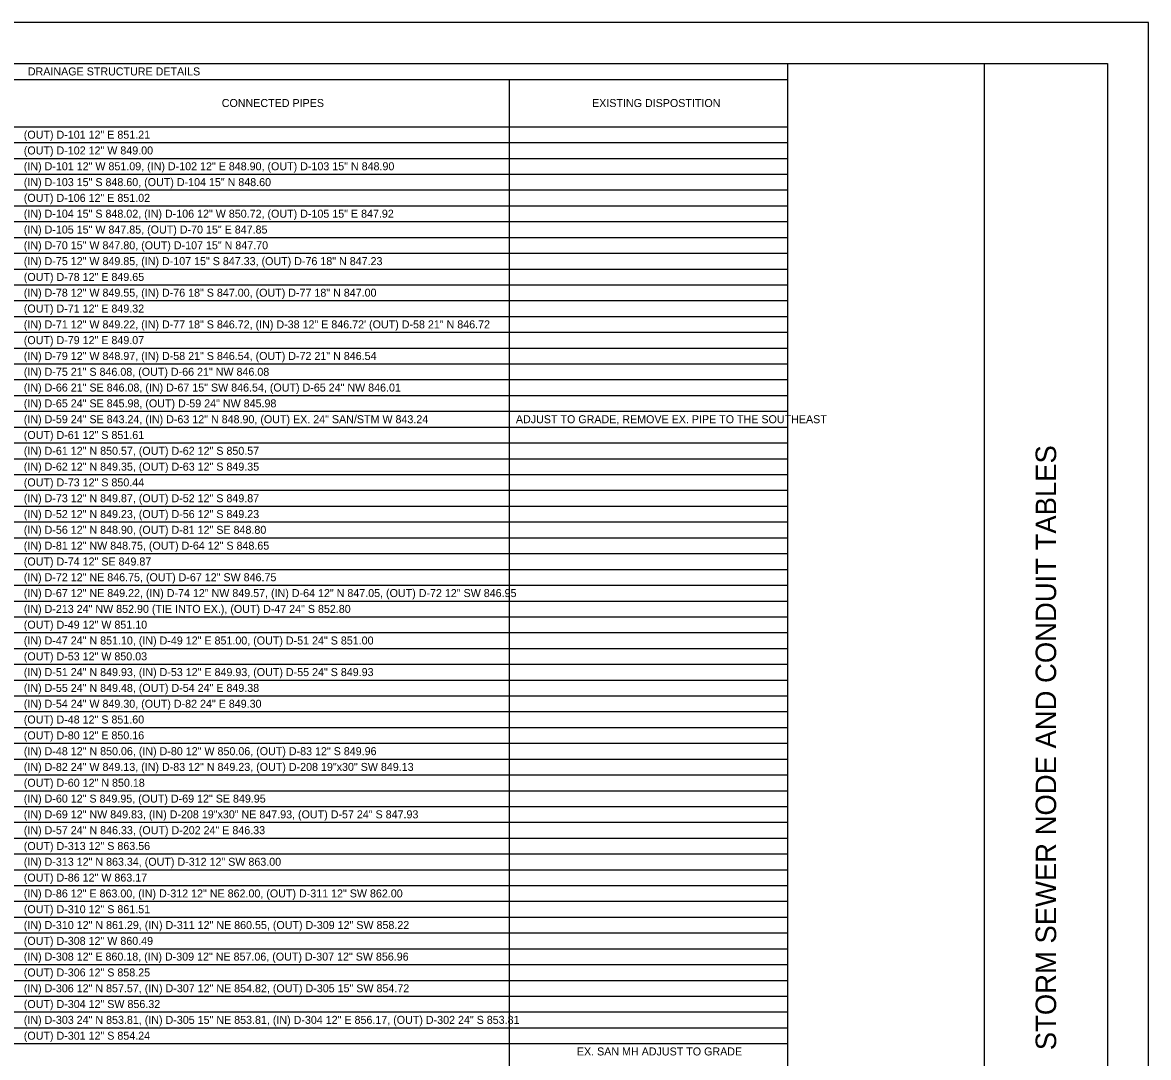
# Model space of a CAD drawing. Extents: x 0 to 34, y 0 to 22.
# Drawn here: x 20.28 to 34, y 9.39 to 22 of the extents above; entities that cross this region are included whole.
import ezdxf

# ---------------------------------------------------------------- set-up
doc = ezdxf.new("R2010")
doc.units = 0
for name, color, linetype in [('SH_Border', 7, 'Continuous'), ('SH_Cut_Line', 7, 'Continuous'), ('SH_Data', 7, 'Continuous'), ('SH_Text', 7, 'Continuous')]:
    doc.layers.add(name, color=color, linetype=linetype)

msp = doc.modelspace()

# ---------------------------------------------------------------- linework, layer by layer
at = {"layer": 'SH_Border'}
msp.add_line((32, 0.5), (32, 21.5), dxfattribs=at)
msp.add_lwpolyline([(1.5, 21.5), (33.5, 21.5), (33.5, 0.5), (1.5, 0.5)], close=True, dxfattribs=at)
at = {"layer": 'SH_Cut_Line'}
msp.add_lwpolyline([(0, 0), (34, 0), (34, 22), (0, 22)], close=True, dxfattribs=at)
at = {"layer": 'SH_Text'}
for p, q in [((12.897, 21.5), (29.601, 21.5)), ((29.601, 21.5), (29.601, 0.5)), ((12.897, 21.307), (29.601, 21.307)), ((26.21, 21.307), (26.21, 0.5)), ((12.897, 20.729), (29.601, 20.729)), ((13.466, 20.537), (29.601, 20.537)), ((13.466, 20.344), (29.601, 20.344)), ((13.466, 20.151), (29.601, 20.151)), ((13.466, 19.959), (29.601, 19.959)), ((13.466, 19.766), (29.601, 19.766)), ((13.466, 19.573), (29.601, 19.573)), ((13.466, 19.381), (29.601, 19.381)), ((13.466, 19.188), (29.601, 19.188)), ((13.466, 18.995), (29.601, 18.995)), ((13.466, 18.803), (29.601, 18.803)), ((13.466, 18.61), (29.601, 18.61)), ((13.466, 18.417), (29.601, 18.417)), ((13.466, 18.225), (29.601, 18.225)), ((13.466, 18.032), (29.601, 18.032)), ((13.466, 17.839), (29.601, 17.839)), ((13.466, 17.647), (29.601, 17.647)), ((13.466, 17.454), (29.601, 17.454)), ((13.466, 17.261), (29.601, 17.261)), ((13.466, 17.069), (29.601, 17.069)), ((13.466, 16.876), (29.601, 16.876)), ((13.466, 16.683), (29.601, 16.683)), ((13.466, 16.491), (29.601, 16.491)), ((13.466, 16.298), (29.601, 16.298)), ((13.466, 16.105), (29.601, 16.105)), ((13.466, 15.913), (29.601, 15.913)), ((13.466, 15.72), (29.601, 15.72)), ((13.466, 15.527), (29.601, 15.527)), ((13.466, 15.335), (29.601, 15.335)), ((13.466, 15.142), (29.601, 15.142)), ((12.897, 14.949), (29.601, 14.949)), ((13.466, 14.757), (29.601, 14.757)), ((13.466, 14.564), (29.601, 14.564)), ((13.466, 14.371), (29.601, 14.371)), ((13.466, 14.179), (29.601, 14.179)), ((13.466, 13.986), (29.601, 13.986)), ((13.466, 13.793), (29.601, 13.793)), ((13.466, 13.601), (29.601, 13.601)), ((13.466, 13.408), (29.601, 13.408)), ((13.466, 13.215), (29.601, 13.215)), ((13.466, 13.023), (29.601, 13.023)), ((13.466, 12.83), (29.601, 12.83)), ((13.466, 12.637), (29.601, 12.637)), ((13.466, 12.445), (29.601, 12.445)), ((13.466, 12.252), (29.601, 12.252)), ((12.897, 12.059), (29.601, 12.059)), ((13.466, 11.867), (29.601, 11.867)), ((13.466, 11.674), (29.601, 11.674)), ((13.466, 11.481), (29.601, 11.481)), ((13.466, 11.289), (29.601, 11.289)), ((13.466, 11.096), (29.601, 11.096)), ((13.466, 10.903), (29.601, 10.903)), ((13.466, 10.711), (29.601, 10.711)), ((13.466, 10.518), (29.601, 10.518)), ((13.466, 10.325), (29.601, 10.325)), ((13.466, 10.133), (29.601, 10.133)), ((13.466, 9.94), (29.601, 9.94)), ((13.466, 9.747), (29.601, 9.747)), ((12.897, 9.555), (29.601, 9.555))]:
    msp.add_line(p, q, dxfattribs=at)

# ---------------------------------------------------------------- texts
at = {"layer": 'SH_Data'}
msp.add_text('STORM SEWER NODE AND CONDUIT TABLES', height=0.25, rotation=90, dxfattribs=at).set_placement((32.875, 9.474))
at = {"layer": 'SH_Text'}
for s, p in [('DRAINAGE STRUCTURE DETAILS', (20.345, 21.355)), ('CONNECTED PIPES', (22.708, 20.97)), ('EXISTING DISPOSTITION', (27.22, 20.97)), ('(OUT) D-101 12" E 851.21', (20.296, 20.584)), ('(OUT) D-102 12" W 849.00', (20.296, 20.392)), ('(IN) D-101 12" W 851.09, (IN) D-102 12" E 848.90, (OUT) D-103 15" N 848.90', (20.296, 20.199)), ('(IN) D-103 15" S 848.60, (OUT) D-104 15" N 848.60', (20.296, 20.006)), ('(OUT) D-106 12" E 851.02', (20.296, 19.814)), ('(IN) D-104 15" S 848.02, (IN) D-106 12" W 850.72, (OUT) D-105 15" E 847.92', (20.296, 19.621)), ('(IN) D-105 15" W 847.85, (OUT) D-70 15" E 847.85', (20.296, 19.428)), ('(IN) D-70 15" W 847.80, (OUT) D-107 15" N 847.70', (20.296, 19.236)), ('(IN) D-75 12" W 849.85, (IN) D-107 15" S 847.33, (OUT) D-76 18" N 847.23', (20.296, 19.043)), ('(OUT) D-78 12" E 849.65', (20.296, 18.85)), ('(IN) D-78 12" W 849.55, (IN) D-76 18" S 847.00, (OUT) D-77 18" N 847.00', (20.296, 18.658)), ('(OUT) D-71 12" E 849.32', (20.296, 18.465)), ('(IN) D-71 12" W 849.22, (IN) D-77 18" S 846.72, (IN) D-38 12" E 846.72\' (OUT) D-58 21" N 846.72', (20.296, 18.272)), ('(OUT) D-79 12" E 849.07', (20.296, 18.08)), ('(IN) D-79 12" W 848.97, (IN) D-58 21" S 846.54, (OUT) D-72 21" N 846.54', (20.296, 17.887)), ('(IN) D-75 21" S 846.08, (OUT) D-66 21" NW 846.08', (20.296, 17.694)), ('(IN) D-66 21" SE 846.08, (IN) D-67 15" SW 846.54, (OUT) D-65 24" NW 846.01', (20.296, 17.502)), ('(IN) D-65 24" SE 845.98, (OUT) D-59 24" NW 845.98', (20.296, 17.309)), ('(IN) D-59 24" SE 843.24, (IN) D-63 12" N 848.90, (OUT) EX. 24" SAN/STM W 843.24', (20.296, 17.116)), ('ADJUST TO GRADE, REMOVE EX. PIPE TO THE SOUTHEAST', (26.292, 17.116)), ('(OUT) D-61 12" S 851.61', (20.296, 16.924)), ('(IN) D-61 12" N 850.57, (OUT) D-62 12" S 850.57', (20.296, 16.731)), ('(IN) D-62 12" N 849.35, (OUT) D-63 12" S 849.35', (20.296, 16.538)), ('(OUT) D-73 12" S 850.44', (20.296, 16.346)), ('(IN) D-73 12" N 849.87, (OUT) D-52 12" S 849.87', (20.296, 16.153)), ('(IN) D-52 12" N 849.23, (OUT) D-56 12" S 849.23', (20.296, 15.96)), ('(IN) D-56 12" N 848.90, (OUT) D-81 12" SE 848.80', (20.296, 15.768)), ('(IN) D-81 12" NW 848.75, (OUT) D-64 12" S 848.65', (20.296, 15.575)), ('(OUT) D-74 12" SE 849.87', (20.296, 15.382)), ('(IN) D-72 12" NE 846.75, (OUT) D-67 12" SW 846.75', (20.296, 15.19)), ('(IN) D-67 12" NE 849.22, (IN) D-74 12" NW 849.57, (IN) D-64 12" N 847.05, (OUT) D-72 12" SW 846.95', (20.296, 14.997)), ('(IN) D-213 24" NW 852.90 (TIE INTO EX.), (OUT) D-47 24" S 852.80', (20.296, 14.804)), ('(OUT) D-49 12" W 851.10', (20.296, 14.612)), ('(IN) D-47 24" N 851.10, (IN) D-49 12" E 851.00, (OUT) D-51 24" S 851.00', (20.296, 14.419)), ('(OUT) D-53 12" W 850.03', (20.296, 14.226)), ('(IN) D-51 24" N 849.93, (IN) D-53 12" E 849.93, (OUT) D-55 24" S 849.93', (20.296, 14.034)), ('(IN) D-55 24" N 849.48, (OUT) D-54 24" E 849.38', (20.296, 13.841)), ('(IN) D-54 24" W 849.30, (OUT) D-82 24" E 849.30', (20.296, 13.648)), ('(OUT) D-48 12" S 851.60', (20.296, 13.456)), ('(OUT) D-80 12" E 850.16', (20.296, 13.263)), ('(IN) D-48 12" N 850.06, (IN) D-80 12" W 850.06, (OUT) D-83 12" S 849.96', (20.296, 13.07)), ('(IN) D-82 24" W 849.13, (IN) D-83 12" N 849.23, (OUT) D-208 19"x30" SW 849.13', (20.296, 12.878)), ('(OUT) D-60 12" N 850.18', (20.296, 12.685)), ('(IN) D-60 12" S 849.95, (OUT) D-69 12" SE 849.95', (20.296, 12.492)), ('(IN) D-69 12" NW 849.83, (IN) D-208 19"x30" NE 847.93, (OUT) D-57 24" S 847.93', (20.296, 12.3)), ('(IN) D-57 24" N 846.33, (OUT) D-202 24" E 846.33', (20.296, 12.107)), ('(OUT) D-313 12" S 863.56', (20.296, 11.914)), ('(IN) D-313 12" N 863.34, (OUT) D-312 12" SW 863.00', (20.296, 11.722)), ('(OUT) D-86 12" W 863.17', (20.296, 11.529)), ('(IN) D-86 12" E 863.00, (IN) D-312 12" NE 862.00, (OUT) D-311 12" SW 862.00', (20.296, 11.336)), ('(OUT) D-310 12" S 861.51', (20.296, 11.144)), ('(IN) D-310 12" N 861.29, (IN) D-311 12" NE 860.55, (OUT) D-309 12" SW 858.22', (20.296, 10.951)), ('(OUT) D-308 12" W 860.49', (20.296, 10.758)), ('(IN) D-308 12" E 860.18, (IN) D-309 12" NE 857.06, (OUT) D-307 12" SW 856.96', (20.296, 10.566)), ('(OUT) D-306 12" S 858.25', (20.296, 10.373)), ('(IN) D-306 12" N 857.57, (IN) D-307 12" NE 854.82, (OUT) D-305 15" SW 854.72', (20.296, 10.18)), ('(OUT) D-304 12" SW 856.32', (20.296, 9.988)), ('(IN) D-303 24" N 853.81, (IN) D-305 15" NE 853.81, (IN) D-304 12" E 856.17, (OUT) D-302 24" S 853.81', (20.296, 9.795)), ('(OUT) D-301 12" S 854.24', (20.296, 9.602)), ('EX. SAN MH ADJUST TO GRADE', (27.035, 9.41))]:
    msp.add_text(s, height=0.09749, dxfattribs=at).set_placement(p)

doc.saveas('drawing.dxf')
